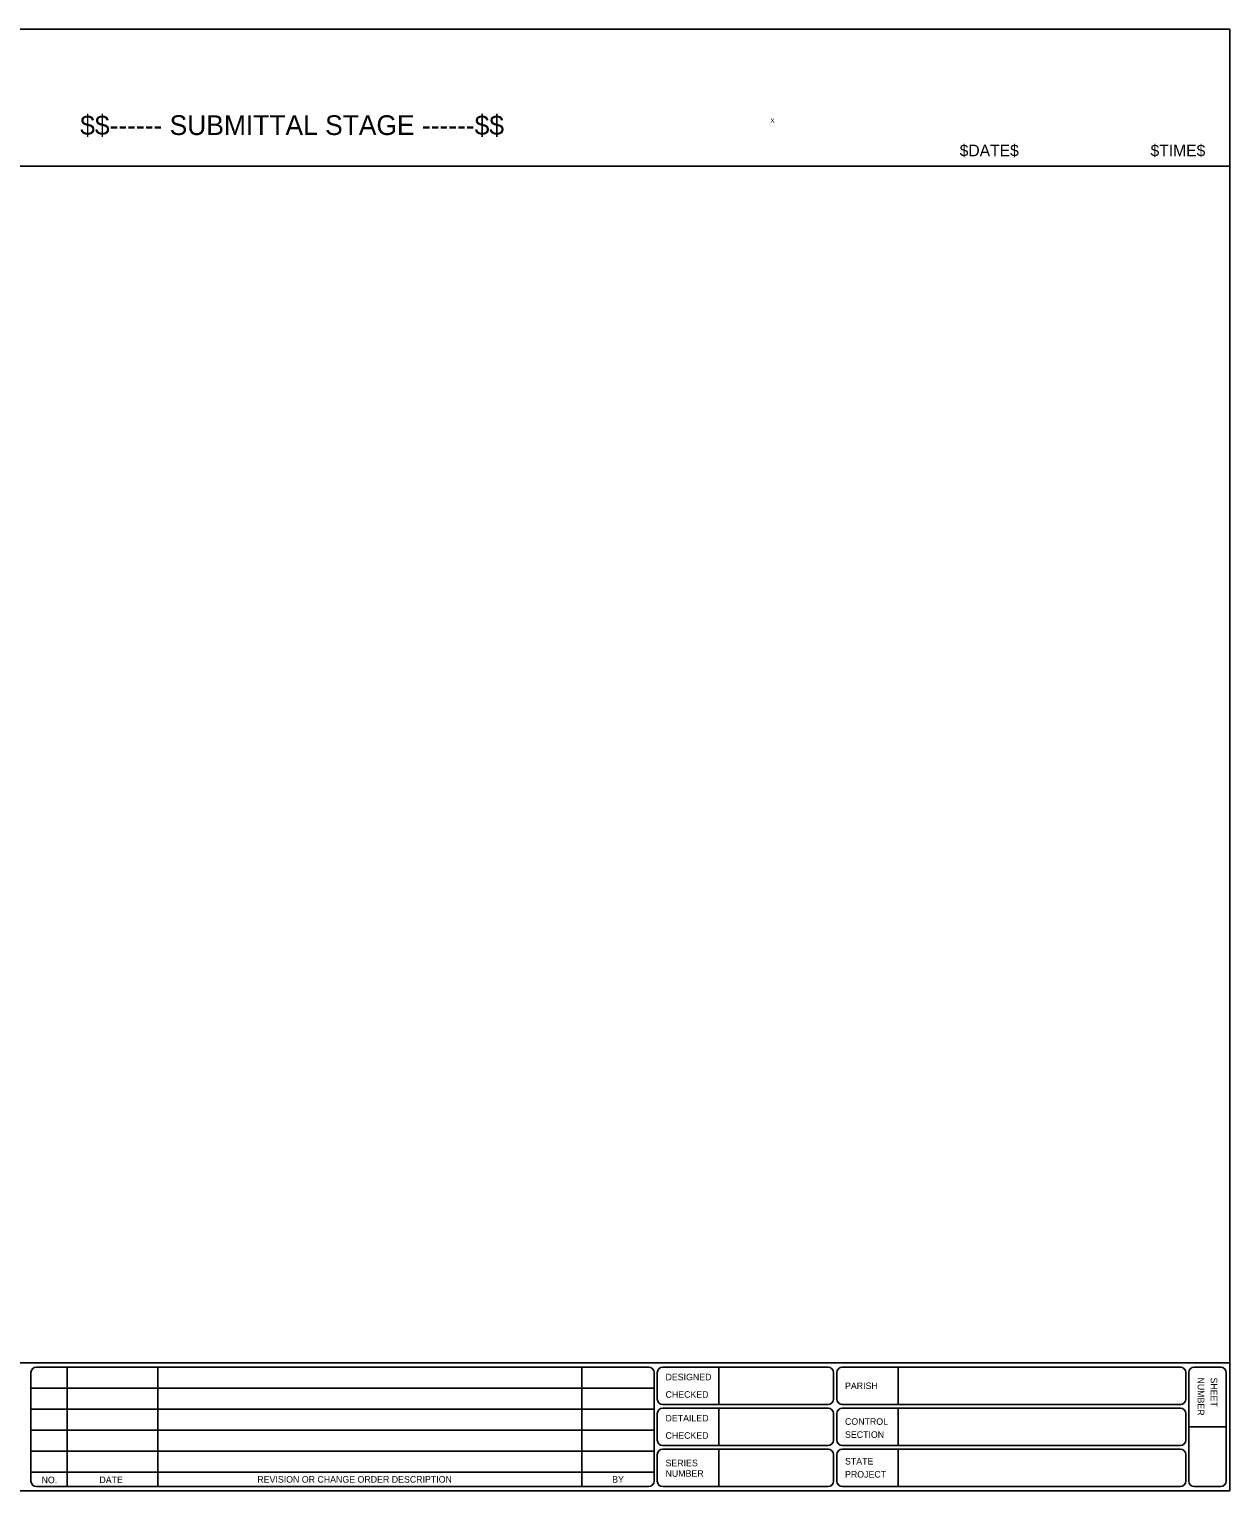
# Model space of a CAD drawing. Extents: x 0 to 21, y 0 to 16.
# Drawn here: x 7.86 to 21, y 0 to 16 of the extents above; entities that cross this region are included whole.
import ezdxf

# ---------------------------------------------------------------- set-up
doc = ezdxf.new("R2010")
doc.units = 0
for name, color, linetype in [('Construction Class', 7, 'Continuous'), ('Plot Border', 7, 'Continuous'), ('Sheet Border', 7, 'Continuous')]:
    doc.layers.add(name, color=color, linetype=linetype)

msp = doc.modelspace()

# ---------------------------------------------------------------- linework, layer by layer
at = {"layer": 'Construction Class'}
msp.add_line((16, 15), (16, 15), dxfattribs=at)
at = {"layer": 'Plot Border'}
msp.add_lwpolyline([(21, 0), (21, 16), (0, 16), (0, 0)], close=True, dxfattribs=at)
at = {"layer": 'Sheet Border'}
for p, q in [((21, 14.5), (0, 14.5)), ((21, 0), (21, 14.5)), ((21, 1.4), (0, 1.4)), ((7.882, 1.294), (7.882, 0.106)), ((14.643, 1.354), (7.941, 1.354)), ((8.278, 1.354), (8.278, 0.046)), ((9.269, 1.354), (9.269, 0.046)), ((13.909, 0.046), (13.909, 1.354)), ((14.701, 0.106), (14.701, 1.294)), ((14.736, 1.004), (14.736, 1.294)), ((16.608, 1.354), (14.796, 1.354)), ((15.41, 0.945), (15.41, 1.354)), ((16.663, 1.004), (16.663, 1.294)), ((16.699, 1.004), (16.699, 1.294)), ((20.464, 1.354), (16.754, 1.354)), ((17.373, 0.945), (17.373, 1.354)), ((20.52, 1.004), (20.52, 1.294)), ((20.551, 0.106), (20.551, 1.294)), ((20.901, 1.354), (20.611, 1.354)), ((20.96, 0.106), (20.96, 1.294)), ((14.701, 1.124), (7.882, 1.124)), ((14.701, 0.894), (7.882, 0.894)), ((14.736, 0.554), (14.736, 0.845)), ((16.603, 0.944), (14.796, 0.944)), ((16.608, 0.905), (14.796, 0.905)), ((15.41, 0.495), (15.41, 0.905)), ((16.663, 0.554), (16.663, 0.845)), ((16.699, 0.555), (16.699, 0.846)), ((20.465, 0.945), (16.754, 0.945)), ((20.46, 0.905), (16.759, 0.905)), ((17.373, 0.495), (17.373, 0.905)), ((20.52, 0.555), (20.52, 0.846)), ((14.701, 0.664), (7.882, 0.664)), ((20.96, 0.7), (20.551, 0.7)), ((16.603, 0.495), (14.796, 0.495)), ((20.461, 0.495), (16.758, 0.495)), ((14.701, 0.435), (7.882, 0.435)), ((14.736, 0.105), (14.736, 0.396)), ((16.608, 0.455), (14.796, 0.455)), ((15.41, 0.046), (15.41, 0.456)), ((16.663, 0.105), (16.663, 0.396)), ((16.699, 0.106), (16.699, 0.396)), ((20.46, 0.456), (16.759, 0.456)), ((17.373, 0.046), (17.373, 0.456)), ((20.52, 0.106), (20.52, 0.396)), ((14.701, 0.205), (7.882, 0.205)), ((21, 0), (0, 0)), ((14.643, 0.046), (7.941, 0.046)), ((16.603, 0.046), (14.796, 0.046)), ((20.46, 0.046), (16.759, 0.046)), ((20.901, 0.046), (20.611, 0.046))]:
    msp.add_line(p, q, dxfattribs=at)
for centre, start, end in [((7.941, 1.294), 90, 180), ((14.643, 1.294), 360, 90), ((14.795, 1.294), 90, 180), ((16.604, 1.294), 360, 90), ((16.759, 1.294), 90, 180), ((20.46, 1.294), 360, 90), ((20.61, 1.294), 90, 180), ((20.901, 1.294), 360, 90), ((14.795, 1.004), 180, 270), ((16.604, 1.004), 270, 360), ((16.759, 1.004), 180, 270), ((20.46, 1.004), 270, 360), ((14.795, 0.845), 90, 180), ((16.604, 0.845), 360, 90), ((16.759, 0.845), 90, 180), ((20.46, 0.845), 360, 90), ((14.795, 0.555), 180, 270), ((16.604, 0.555), 270, 360), ((16.759, 0.555), 180, 270), ((20.46, 0.555), 270, 360), ((14.795, 0.396), 90, 180), ((16.604, 0.396), 360, 90), ((16.759, 0.396), 90, 180), ((20.46, 0.396), 360, 90), ((7.941, 0.106), 180, 270), ((14.643, 0.106), 270, 360), ((14.795, 0.105), 180, 270), ((16.604, 0.105), 270, 360), ((16.759, 0.106), 180, 270), ((20.46, 0.106), 270, 360), ((20.61, 0.106), 180, 270), ((20.901, 0.106), 270, 360)]:
    msp.add_arc(centre, 0.0594, start, end, dxfattribs=at)

# ---------------------------------------------------------------- texts
at = {"layer": 'Plot Border'}
for s, height, p in [('$$------ SUBMITTAL STAGE ------$$', 0.216, (8.421, 14.842)), ('$DATE$', 0.128, (18.045, 14.609)), ('$TIME$', 0.128, (20.133, 14.609))]:
    msp.add_text(s, height=height, rotation=360, dxfattribs=at).set_placement(p)
at = {"layer": 'Sheet Border'}
msp.add_text('X', height=0.05, dxfattribs=at).set_placement((15.973, 14.975))
for s, rotation, p in [('DESIGNED', 360, (14.826, 1.209)), ('PARISH', 360, (16.79, 1.113)), ('NUMBER', 270, (20.649, 1.24)), ('SHEET', 270, (20.792, 1.24)), ('CHECKED', 360, (14.826, 1.018)), ('DETAILED', 360, (14.826, 0.759)), ('CHECKED', 360, (14.826, 0.569)), ('CONTROL', 360, (16.79, 0.722)), ('SECTION', 360, (16.79, 0.579)), ('SERIES', 360, (14.826, 0.268)), ('STATE', 360, (16.79, 0.287)), ('REVISION OR CHANGE ORDER DESCRIPTION', 360, (10.359, 0.089)), ('BY', 360, (14.242, 0.089)), ('NUMBER', 360, (14.826, 0.153)), ('PROJECT', 360, (16.79, 0.144)), ('NO.', 360, (7.998, 0.083)), ('DATE', 360, (8.631, 0.084))]:
    msp.add_text(s, height=0.072, rotation=rotation, dxfattribs=at).set_placement(p)

doc.saveas('drawing.dxf')
